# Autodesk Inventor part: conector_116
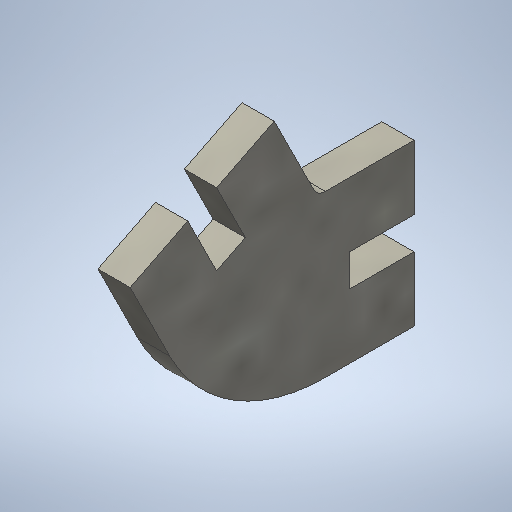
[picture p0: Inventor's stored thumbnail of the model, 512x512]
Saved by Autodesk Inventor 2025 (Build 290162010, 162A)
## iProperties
Created: 2025-02
Part Number: conector_116
Material: Paper
Document SubType Name: Modeling
Designer: BennF
Density: 0.93 g/cm^3
Appearance: Cardboard - Chipboard
Author: BennF
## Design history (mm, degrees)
sketch "Sketch2"
  geometry: L1 (0, -1)-(6.882, -1); L2 (6.882, -1)-(6.882, -6); L3 (6.882, -6)-(1.882, -6); L4 (1.882, -6)-(1.882, -8.5); L5 (1.882, -8.5)-(6.882, -8.5); L6 (6.882, -8.5)-(6.882, -13.5); L7 (6.882, -13.5)-(0, -13.5); L8 (-0.894, -0.447)-(-3.972, 5.708); L9 (-3.972, 5.708)-(-8.444, 3.472); L10 (-8.444, 3.472)-(-6.208, -1); L11 (-6.208, -1)-(-8.444, -2.118); L12 (-8.444, -2.118)-(-10.68, 2.354); L13 (-10.68, 2.354)-(-15.152, 0.118); L14 (-15.152, 0.118)-(-12.075, -6.037); L15 (-6.208, -1)-(1.882, -6); A1 r 1 centre (0, 0) between (-0.894, -0.447) and (0, -1); A2 r 13.5 centre (0, 0) between (-12.075, -6.037) and (0, -13.5); 1 further point
  constraints: 30 end point, 10 perpendicular, 5 equal length, 4 point on circle, 4 point on line, 4 tangent, 2 centre point, 2 coincident, 1 horizontal
  dimensions: "d0" = 1 radius of A1; "d1" = 2.5 distance of L3.end L4.end (= thickness); "d2" = 5 distance of L2.end L3.end (= slot_depth); "d3" = 5 distance of L1.end L2.end (= slot_dis_1); "d4" = 116.565 deg angle of L1 L8 (= con_angle_1); "d5" = 5 vertical distance of L10.end L3.end (computed from slot_clearenece)
extrude "Extrusion1" new body sketch "Sketch2" distance "d6" = 2.5 (= thickness); taper "d7" = 0 deg
sketch "laser"
  geometry: L1 (-3.472, -8.444)-(1, -6.208) reference; L2 (1, -6.208)-(2.118, -8.444) reference; L3 (2.118, -8.444)-(-2.354, -10.68) reference; L4 (-2.354, -10.68)-(-0.118, -15.152) reference; L5 (-0.118, -15.152)-(6.037, -12.075) reference; L6 (13.5, 0)-(13.5, 6.882) reference; L7 (13.5, 6.882)-(8.5, 6.882) reference; L8 (8.5, 6.882)-(8.5, 1.882) reference; L9 (8.5, 1.882)-(6, 1.882) reference; L10 (6, 1.882)-(6, 6.882) reference; L11 (6, 6.882)-(1, 6.882) reference; L12 (1, 6.882)-(1, 0) reference; L13 (0.447, -0.894)-(-5.708, -3.972) reference; L14 (-5.708, -3.972)-(-3.472, -8.444) reference; A1 r 13.5 centre (0, 0) between (6.037, -12.075) and (13.5, 0) reference; A2 r 1 centre (0, 0) between (0.447, -0.894) and (1, 0) reference; 1 further point
  node "Projected Loop1"
body "Solid1"
other parameters: "thickness" = 2.5 [user parameter; used in 2 equation terms], "clearence" = -0.5 [user parameter], "slot_depth" = 5 [user parameter; used in 1 equation term], "slot_dis_1" = 5 [user parameter; used in 1 equation term], "slot_dis_2" = 12 [user parameter], "slot_clearenece" = 3 [user parameter; used in 1 equation term], "con_angle_1" = 116.565 deg [user parameter; used in 1 equation term], "con_angle_2" = 60 deg [user parameter], "con_angle_3" = 12.30959 [user parameter], "con_angle_4" = 19.10633 [user parameter], "con_angle_5" = 24.11865 [user parameter]
